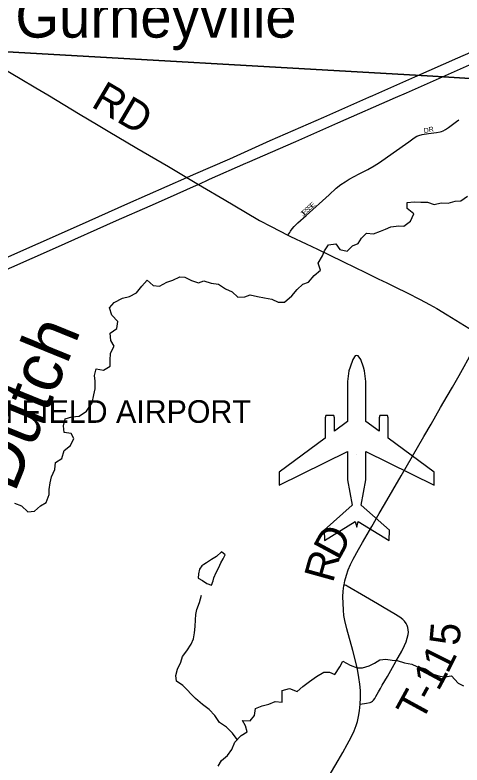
# Model space of a CAD drawing. Extents: x 1442749 to 1756758, y 235267 to 677782.
# Drawn here: x 1580655 to 1585086, y 547513 to 554957 of the extents above; entities that cross this region are included whole.
import ezdxf

# ---------------------------------------------------------------- set-up
doc = ezdxf.new("R2010")
doc.units = 0
for name, color, linetype in [('GM_X_Airport_Class_2', 7, 'Continuous'), ('GM_X_Airport_Location_Class_2', 7, 'Continuous'), ('GM_X_Airport_Text_Class_2', 7, 'Continuous'), ('GM_X_County_Road', 7, 'Continuous'), ('GM_X_County_Road_Text', 7, 'Continuous'), ('GM_X_Interstate_Route', 7, 'Continuous'), ('GM_X_Minor_Lake', 7, 'Continuous'), ('GM_X_Minor_River', 7, 'Continuous'), ('GM_X_Minor_River_Text', 7, 'Continuous'), ('GM_X_Township', 7, 'Continuous'), ('GM_X_Township_Road', 7, 'Continuous'), ('GM_X_Township_Road_Text', 7, 'Continuous'), ('GM_X_Township_Subdivision', 7, 'Continuous'), ('GM_X_Township_Subdivision_Text', 7, 'Continuous'), ('GM_X_Unincorporated_Text', 7, 'Continuous')]:
    doc.layers.add(name, color=color, linetype=linetype)

msp = doc.modelspace()

# ---------------------------------------------------------------- linework, layer by layer
at = {"layer": 'GM_X_Airport_Class_2'}
msp.add_lwpolyline([(1583729.8, 550757), (1583273.4, 550419.5), (1583273.4, 550290), (1583952.4, 550624.6), (1583952.4, 550342.8), (1583997.5, 550093.4), (1583718.1, 549842.8), (1583722.5, 549739.6), (1584028.5, 549929.3), (1584042.6, 549873.8), (1584056.7, 549929.3), (1584362.8, 549739.6), (1584367.1, 549842.8), (1584087.7, 550093.4), (1584132.8, 550342.8), (1584132.8, 550624.6), (1584811.8, 550290), (1584811.8, 550419.5), (1584355.4, 550757), (1584355.4, 550958.5), (1584348.3, 550983), (1584270.6, 550983), (1584263.5, 550958.5), (1584263.5, 550824.9), (1584132.8, 550921.6), (1584132.8, 550921.6), (1584132.8, 551319.5), (1584119.7, 551424.7), (1584108.7, 551462.2), (1584081.7, 551538.8), (1584056.8, 551572.8), (1584042.6, 551578.8), (1584028.4, 551572.8), (1584003.5, 551538.8), (1583976.5, 551462.2), (1583965.6, 551424.7), (1583952.4, 551319.5), (1583952.4, 550921.6), (1583821.7, 550824.9), (1583821.7, 550958.5), (1583814.6, 550983), (1583736.9, 550983), (1583729.8, 550958.5)], close=True, dxfattribs=at)
at = {"layer": 'GM_X_Airport_Location_Class_2'}
msp.add_line((1584042.6, 550596.2), (1584042.6, 550596.2), dxfattribs=at)
at = {"layer": 'GM_X_County_Road'}
for points in [[(1580455.2, 554476.2), (1580558.9, 554413.6), (1580706.1, 554327.2), (1580860.8, 554234.6), (1580978.8, 554163.5), (1581299.2, 553970.7), (1581462.9, 553873.9), (1581578.4, 553805.2), (1581863.8, 553636.8), (1582174.9, 553453.8), (1582358.3, 553344.4), (1582472.4, 553276.4), (1582512.9, 553252.2), (1582727.2, 553124.8), (1582938.6, 552998.9), (1583077.8, 552918.3), (1583193.6, 552856.5), (1583361, 552772.1)], [(1583361, 552772.1), (1583386.8, 552759), (1583540.4, 552685.3), (1583653, 552631.8), (1583767.9, 552575.7), (1583912.6, 552505.7), (1584021.8, 552453.1), (1584130.6, 552399.7), (1584210, 552361), (1584254.3, 552339.6), (1584339.9, 552298.4), (1584425.5, 552257), (1584543, 552198.7), (1584671.7, 552133.6), (1584764.5, 552085), (1584835.9, 552044.9), (1584939.9, 551982.7), (1585026, 551928.7), (1585153.8, 551848.4), (1585285.6, 551767.4)], [(1583918.3, 549302.1), (1583925.9, 549341), (1583940.9, 549397.8), (1583958.5, 549450.3), (1583979.7, 549501.5), (1584007.1, 549557.1), (1584059, 549651.8), (1584098.7, 549719.6), (1584192.5, 549881.3), (1584265.8, 550009.4), (1584318.6, 550100), (1584483.1, 550383.8), (1584707.9, 550772.9), (1584779.5, 550894.3), (1584874.5, 551062.8), (1584939, 551173.2), (1584992.2, 551263.6), (1585059.1, 551380.2), (1585091.3, 551437.3), (1585162.1, 551563), (1585215.7, 551653.1), (1585268.7, 551739.7), (1585285.6, 551767.4)], [(1584076.8, 548118), (1584080.8, 548180.3), (1584081, 548189.4), (1584079.2, 548251.9), (1584074.1, 548314.2), (1584064.4, 548382.6), (1584049.2, 548463.3), (1584030.2, 548546.5), (1584003.9, 548648.3), (1583945.1, 548863.4), (1583925.3, 548946), (1583916.1, 548997.4), (1583910.1, 549049.1), (1583906.4, 549117.6), (1583906.1, 549182.9), (1583909.5, 549238.2), (1583915.9, 549289.9), (1583918.3, 549302.1)], [(1583757.7, 547388.7), (1583857.3, 547558), (1583903.9, 547637.2), (1583946.8, 547714.7), (1583986.9, 547790.2), (1584016.2, 547852.8), (1584037, 547904.9), (1584049.9, 547945.8), (1584061.4, 547994), (1584070.7, 548049.3), (1584076.8, 548118)]]:
    msp.add_lwpolyline(points, dxfattribs=at)
at = {"layer": 'GM_X_Interstate_Route'}
for points in [[(1582941.8, 553485.6), (1582960.8, 553494.1), (1583439.4, 553701.5), (1583856, 553887), (1584427, 554138.7), (1584534.5, 554186), (1585814.8, 554754.5), (1586532.5, 555070.4), (1587158.2, 555346.7), (1587414.1, 555461.7), (1588140.7, 555781.7), (1588379.6, 555885.7)], [(1580470, 552508.1), (1581295.4, 552872.2), (1581774.5, 553086.6), (1582358.3, 553344.4), (1582425.7, 553374.2), (1582783.9, 553529.4), (1583184.7, 553710.2), (1583716.3, 553943.7), (1584163.6, 554140.9), (1584203.3, 554158.6), (1584619.1, 554343.8), (1585045.8, 554530.9), (1585658, 554801.3), (1586035.6, 554969.6)], [(1582454.3, 553268.3), (1582472.4, 553276.4), (1582583, 553326.2), (1582941.8, 553485.6)], [(1580387.8, 552352.6), (1581057.3, 552647.7), (1581659.3, 552916.7), (1581996, 553063.3), (1582167.2, 553139), (1582454.3, 553268.3)]]:
    msp.add_lwpolyline(points, dxfattribs=at)
at = {"layer": 'GM_X_Minor_Lake'}
for points in [[(1582624.7, 549370.2), (1582647.6, 549424.6), (1582676.5, 549474.2), (1582695.3, 549518), (1582718, 549559.8), (1582736.7, 549599.6), (1582701.2, 549628.2), (1582652.3, 549582.9), (1582601.7, 549551.6), (1582553, 549518.3), (1582528.2, 549503.1)], [(1582528.2, 549503.1), (1582508.4, 549490.9), (1582483.8, 549455.2), (1582475, 549411.3), (1582470.2, 549367.2), (1582513.9, 549342.5), (1582555.5, 549315.8), (1582603.3, 549299), (1582618.1, 549340.8), (1582624.7, 549370.2)]]:
    msp.add_lwpolyline(points, dxfattribs=at)
at = {"layer": 'GM_X_Minor_River'}
for points in [[(1584878.8, 553091.8), (1584948.9, 553090.6), (1585017.3, 553109.6), (1585075.5, 553112.7), (1585140.4, 553157.8)], [(1580649.7, 550112), (1580717.3, 550084.9), (1580782.4, 550025.7), (1580846.6, 550030.7), (1580907.7, 550083.9), (1580962.4, 550119.1), (1580993.8, 550196.7), (1580994.6, 550248.9), (1581001.8, 550314.9), (1581014.8, 550372.8), (1581048.1, 550446.5), (1581055.3, 550514.5), (1581118.1, 550553.6), (1581141.6, 550635.4), (1581204.5, 550682.5), (1581237.8, 550752.2), (1581210.6, 550802.7), (1581142.6, 550811.8), (1581135.7, 550878.1), (1581153, 550948), (1581219.4, 550967), (1581291.7, 550973.8), (1581362.7, 551024.8), (1581420.2, 551108.1), (1581437.6, 551188), (1581450.6, 551246), (1581450, 551324.2), (1581442.9, 551378.4), (1581458.1, 551446.3), (1581532, 551433.1), (1581596.8, 551472.2), (1581597.7, 551526.3), (1581601, 551600.4), (1581638.3, 551670), (1581603.2, 551726.7), (1581598.4, 551798.9), (1581665.4, 551846), (1581674.6, 551916), (1581613.5, 551979.1), (1581590.8, 552051.7), (1581637.8, 552105), (1581720.6, 552145.8), (1581789, 552162.8), (1581857.8, 552197.8), (1581911.1, 552267.1), (1581966.1, 552324.3), (1582023.4, 552273.3), (1582087.4, 552266.2), (1582160.2, 552305.2), (1582220.6, 552324.3), (1582287.3, 552357.3), (1582337.4, 552356.5), (1582404.9, 552321.3), (1582472.7, 552300.2), (1582525.1, 552319.4), (1582600.8, 552294.2), (1582670.8, 552285), (1582742.1, 552237.8), (1582807.7, 552208.7), (1582862.9, 552155.6), (1582933.1, 552160.5), (1582985.6, 552179.7), (1583057.4, 552164.6), (1583127.3, 552151.4), (1583199.2, 552138.2), (1583262.8, 552107.2), (1583327, 552108.1), (1583398.1, 552169.2), (1583453.3, 552232.4), (1583508.3, 552285.7), (1583562.8, 552304.8), (1583622, 552372.1), (1583683.1, 552425.2), (1583660.2, 552493.8), (1583701.5, 552565.3), (1583724.4, 552617), (1583763.5, 552674.5), (1583833.8, 552685.4), (1583875, 552630.7), (1583948.8, 552611.4), (1584001.8, 552666.7), (1584056.3, 552689.9), (1584089.3, 552741.5), (1584138.2, 552792.8), (1584208.2, 552783.7), (1584276.8, 552810.7), (1584327.2, 552829.9), (1584379.8, 552855.1), (1584460.1, 552863.9), (1584510.1, 552861.1), (1584577.1, 552910.1), (1584608.4, 552983.8), (1584543.2, 553035), (1584542.2, 553097.1), (1584610.4, 553102.1), (1584678.5, 553099), (1584744.6, 553099.9), (1584810.4, 553076.8), (1584878.8, 553091.8)], [(1582858.2, 547764.8), (1582812.1, 547830), (1582750.6, 547886.8), (1582681.1, 547933.8), (1582635.8, 548004.5), (1582578.4, 548063.3), (1582512.8, 548112.2), (1582445.4, 548173.1), (1582318.7, 548302.9), (1582257, 548345.7), (1582249.7, 548400), (1582264.5, 548464), (1582297.4, 548533.8), (1582316.1, 548589.7), (1582356.8, 548647.4), (1582399.7, 548713.1), (1582424.4, 548765), (1582435.1, 548823), (1582441.9, 548889.1), (1582444.7, 548953.3), (1582447.3, 549005.4), (1582457.9, 549057.4), (1582484.8, 549125.3), (1582503.7, 549197.3)], [(1582667.9, 547502.7), (1582702.6, 547556.5), (1582761.3, 547607.9), (1582804.1, 547667.6), (1582833.1, 547739.5), (1582898, 547804.9), (1582956.5, 547840.4), (1582939.2, 547902.7), (1582909.8, 547953.2), (1582985.9, 547950.3), (1583028.6, 548004), (1583037.5, 548074.1), (1583105.9, 548099.4), (1583170.3, 548116.7), (1583232.7, 548142), (1583302.8, 548135.2), (1583301.6, 548203.4), (1583302.2, 548253.5), (1583374.5, 548270.8), (1583450.3, 548241.8), (1583509.1, 548293.3), (1583575.8, 548340.7), (1583642.5, 548392), (1583715.2, 548433.3), (1583771.3, 548432.7), (1583825.2, 548412), (1583876.2, 548485.6), (1583904.9, 548543.5), (1583976.6, 548504.5), (1584046.4, 548475.7), (1584100.5, 548477), (1584164.9, 548498.4), (1584217.3, 548523.8), (1584271.9, 548557.3), (1584330, 548562.7), (1584394.1, 548553.9), (1584444.1, 548551.3), (1584516, 548526.4), (1584588, 548513.6), (1584639.8, 548490.9), (1584723.8, 548467.9), (1584801.3, 548414.9), (1584865.2, 548396.1), (1584915.2, 548387.5), (1584981.5, 548396.8), (1585048.8, 548325.8), (1585102.5, 548297.1)]]:
    msp.add_lwpolyline(points, dxfattribs=at)
at = {"layer": 'GM_X_Township'}
for points in [[(1615321.2, 557320.2), (1613178.2, 554457.1), (1611426.7, 552128.9), (1606228.2, 552537.5), (1601614.7, 552911.7), (1598152.7, 553173.2), (1597557.5, 553225.2), (1593926.1, 553600.7), (1589106.2, 554078.6), (1586587.6, 554237.2), (1584797.1, 554350), (1580170.1, 554613.8), (1579969, 554625.3), (1576704.1, 554811.5), (1576813.8, 555881.3)], [(1577335.5, 518378.1), (1577246.7, 522507.3), (1577095.4, 529536.7), (1576886.4, 539252.1), (1576884.4, 539342.6), (1576764.1, 539348.5), (1575500.4, 539411), (1575571.3, 540238.8), (1575630.5, 540930.9), (1575922.4, 544864.2), (1576128.9, 547648.1), (1576189.1, 548397.4), (1576369, 550638.4), (1576385.5, 550843.6), (1576704.1, 554811.5), (1579969, 554625.3), (1580170.1, 554613.8), (1584797.1, 554350), (1586587.6, 554237.2), (1589106.2, 554078.6), (1593926.1, 553600.7)]]:
    msp.add_lwpolyline(points, dxfattribs=at)
at = {"layer": 'GM_X_Township_Road'}
msp.add_lwpolyline([(1584076.8, 548118), (1584140.1, 548125.4), (1584174.9, 548133.5), (1584189.7, 548139.4), (1584200.2, 548146), (1584208.9, 548154.9), (1584220.9, 548173.9), (1584232.8, 548193.5), (1584258.3, 548239.3), (1584277.2, 548273.6), (1584286.7, 548290.6), (1584295.1, 548304.5), (1584346.6, 548391.9), (1584381.1, 548451.4), (1584431.3, 548539.9), (1584489.1, 548642.9), (1584516.9, 548698.4), (1584531.9, 548734.5), (1584543.5, 548771.9), (1584551.4, 548806.9), (1584554.3, 548832.6), (1584554, 548855.2), (1584550.3, 548877.3), (1584543.2, 548898.6), (1584532.8, 548918.5), (1584517.6, 548939.2), (1584499.3, 548957.3), (1584470.7, 548978.6), (1584409.4, 549016.3), (1584313.7, 549073.3), (1584249, 549112.3), (1584130.7, 549182.9), (1583946.8, 549288.7), (1583937.2, 549293.6), (1583926.3, 549298.5), (1583918.3, 549302.1)], dxfattribs=at)
at = {"layer": 'GM_X_Township_Subdivision'}
msp.add_lwpolyline([(1583361, 552772.1), (1583378.5, 552798.9), (1583387, 552812), (1583400.8, 552833.1), (1583421.9, 552857.6), (1583459.4, 552894.8), (1583540, 552967.1), (1583768.8, 553173.5), (1583839.5, 553237.4), (1583885.7, 553274.5), (1583926.4, 553302.7), (1583969, 553327.9), (1584068.2, 553379.1), (1584152.4, 553423), (1584214.6, 553459), (1584269.6, 553494.2), (1584403.7, 553588.4), (1584557.9, 553699.3), (1584611, 553738.4), (1584637.1, 553753.5), (1584659, 553762.1), (1584691.4, 553770.2), (1584753.2, 553780.4), (1584834.2, 553791.7), (1584868.2, 553797.5), (1584884, 553801.5), (1584898.8, 553807.4), (1584922.1, 553821.4), (1584951.8, 553840.9), (1585030.2, 553900.3), (1585054.8, 553917)], dxfattribs=at)

# ---------------------------------------------------------------- texts
at = {"layer": 'GM_X_Airport_Text_Class_2'}
msp.add_text('CLINTON FIELD AIRPORT', height=225, rotation=0.00001, dxfattribs=at).set_placement((1579315.6, 550909))
at = {"layer": 'GM_X_County_Road_Text'}
for s, rotation, p in [('RD', 329.54091, (1581399.1, 554053.3)), ('D', 61.66223, (1583865, 549533.7)), ('R', 74.51348, (1583805.8, 549312.7))]:
    msp.add_text(s, height=300, rotation=rotation, dxfattribs=at).set_placement(p)
at = {"layer": 'GM_X_Minor_River_Text'}
msp.add_text('Dutch', height=499.96, rotation=67.8413, dxfattribs=at).set_placement((1580650.9, 550207.3))
at = {"layer": 'GM_X_Township_Road_Text'}
for s, rotation, p in [('5', 84.81138, (1585059.1, 548690.7)), ('1', 63.68252, (1584944.5, 548409.6)), ('1', 61.72711, (1584851.9, 548237)), ('-', 61.38026, (1584791.9, 548127)), ('T', 61.29923, (1584683.9, 547929.8))]:
    msp.add_text(s, height=300, rotation=rotation, dxfattribs=at).set_placement(p)
at = {"layer": 'GM_X_Township_Subdivision_Text'}
for s, rotation, p in [('DR', 11.88289, (1584712.2, 553782.7)), ('S', 42.39129, (1583577.7, 553015.9)), ('E', 42.37288, (1583603.7, 553039.6)), ('J', 44.44375, (1583510.8, 552952.8)), ('E', 43.2994, (1583526.3, 552968.1)), ('S', 42.6229, (1583551.8, 552992.1))]:
    msp.add_text(s, height=50, rotation=rotation, dxfattribs=at).set_placement(p)
at = {"layer": 'GM_X_Unincorporated_Text'}
msp.add_text('Gurneyville', height=417, rotation=0.00001, dxfattribs=at).set_placement((1580657.6, 554732.5))

doc.saveas('drawing.dxf')
